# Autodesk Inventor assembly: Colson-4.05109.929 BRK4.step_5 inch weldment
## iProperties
Created: 2010-10
Part Number: Colson-4.05109.929 BRK4.step_5 inch weldment
Document SubType Name: Assembly
Designer: Administrator
Author: Administrator
